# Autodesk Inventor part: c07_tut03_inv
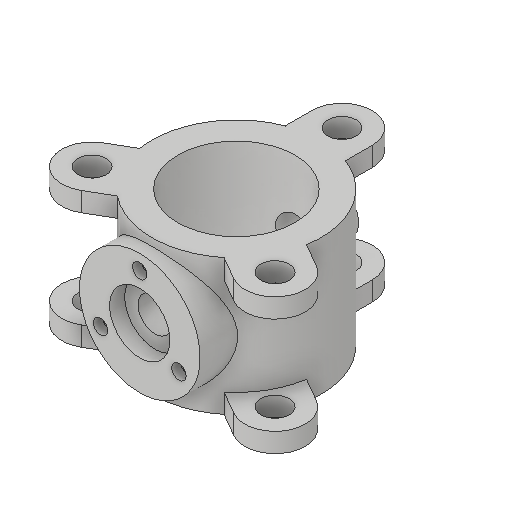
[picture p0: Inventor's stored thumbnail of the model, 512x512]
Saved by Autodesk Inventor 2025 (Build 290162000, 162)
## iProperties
Created: 2017-04
Part Number: c07_tut03_inv
Material: Generic
Document SubType Name: Modeling
Designer: CADCIM 00
Density: 1 g/cm^3
Appearance: Default
Author: CADCIM 00
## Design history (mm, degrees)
sketch "Sketch1"
  geometry: C1 r 140 at (0, 0); C2 r 97 at (0, 0); 1 further point
  constraints: 2 centre point, 2 coincident
  dimensions: "d0" = 280 diameter of C1; "d1" = 194 diameter of C2
extrude "Extrusion1" new body sketch "Sketch1" stored distance "d2" = 225; taper "d3" = 0 deg
workplane "Work Plane1"
sketch "Sketch2"
  geometry: C1 r 100 at (0, 0); 1 further point
  constraints: 1 centre point, 1 coincident
  dimensions: "d5" = 200 diameter of C1
extrude "Extrusion2" join sketch "Sketch2" stored distance "d6" = 225; taper "d7" = 0 deg
workplane "Work Plane2"
sketch "Sketch3"
  geometry: C1 r 37.5 at (0, 0); 1 further point
  constraints: 1 centre point, 1 coincident
  dimensions: "d9" = 75 diameter of C1
extrude "Extrusion3" join sketch "Sketch3" stored distance "d10" = 225; taper "d11" = 0 deg
hole "Hole1" diameter "d14" = 56; stored, may be unused: countersink angle "d18" = 90 deg, drill point angle "d20" = 0 deg; dims "d12" = 10, "d13" = 10, "d15" = 6, "d16" = 100, "d17" = 25, "d19" = 310
sketch "Sketch6"
  geometry: 2 further points
  constraints: 1 vertical alignment
  dimensions: "d21" = 75 distance of point (0, 75) point (0, 0)
hole "Hole2" sketch "Sketch6" diameter "d22" = 24; stored, may be unused: countersink angle "d26" = 90 deg, drill point angle "d28" = 0 deg; dims "d23" = 6, "d24" = 100, "d25" = 25, "d27" = 15
pattern_circular "Circular Pattern1" dims angle "d30" = 360 deg
sketch "Sketch7"
  geometry: L1 (-50, 130.767)-(-50, 175); L2 (50, 175)-(50, 130.767); L3 (0, 0)-(0, 175); C1 r 23.5 at (0, 175); A1 r 50 centre (0, 175) between (50, 175) and (-50, 175); A2 r 140 centre (0, 0) between (-50, 130.767) and (50, 130.767) reference; 1 further point
  constraints: 6 end point, 4 point on circle, 2 centre point, 2 tangent, 2 vertical, 1 coincident, 1 parallel
  dimensions: "d32" = 175 distance of point (0, 0) L3.end; "d34" = 47 diameter of C1; "d40" = 50 radius of A1
extrude "Extrusion4" join sketch "Sketch7" distance "d35" = 32; taper "d36" = 0 deg
pattern_circular "Circular Pattern2" dims angle "d38" = 360 deg
mirror "Mirror1"
body "Solid1"
other parameters: "d8" = 325
